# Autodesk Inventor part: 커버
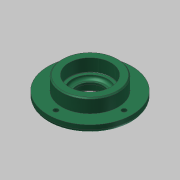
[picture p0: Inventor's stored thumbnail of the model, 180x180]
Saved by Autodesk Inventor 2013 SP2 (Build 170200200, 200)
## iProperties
Company: 한국ATC센터
Created: 2014-10
Part Number: 커버
Document SubType Name: Modeling
Designer: KYOUNG IL JANG
Density: 2.71 g/cm^3
Mass: 121.214 g
Surface Area: 161.165 cm^2
Volume: 44.7286 cm^3
Material: 알루미늄 6061
Author: KYOUNG IL JANG
Revision Number: 1
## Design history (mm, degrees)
sketch "스케치1"
  geometry: C1 r 41 at (0, 0); 1 further point
  constraints: 1 centre point, 1 coincident
  dimensions: "d0" = 82 diameter of C1
extrude "돌출1" new body sketch "스케치1" distance "d1" = 7; taper "d2" = 0 deg
sketch "스케치2"
  geometry: C1 r 27 at (0, 0); 1 further point
  constraints: 1 centre point, 1 coincident
  dimensions: "d3" = 54 diameter of C1
extrude "돌출2" join sketch "스케치2" distance "d4" = 13; taper "d5" = 0 deg
sketch "스케치3"
  geometry: C1 r 20 at (0, 0); 1 further point
  constraints: 1 centre point, 1 coincident
  dimensions: "d6" = 40 diameter of C1
extrude "돌출3" join sketch "스케치3" distance "d7" = 5; taper "d8" = 0 deg
hole "구멍1" diameter "d11" = 25; stored, may be unused: countersink angle "d15" = 90 deg, drill point angle "d17" = 118 deg; dims "d9" = 10, "d10" = 10, "d12" = 6, "d13" = 32, "d14" = 8.3, "d16" = 8
hole "구멍2" diameter "d20" = 34; stored, may be unused: countersink angle "d24" = 90 deg, drill point angle "d26" = 0 deg; dims "d18" = 10, "d19" = 10, "d21" = 6, "d22" = 40, "d23" = 12, "d25" = 3
fillet "모깎기2" dims "d34" = 3
fillet "모깎기1" dims "d27" = 0.3
chamfer "모따기1" distance "d28" = 1; stored, may be unused: second distance "d29" = 2, angle "d30" = 45 deg
chamfer "모따기2" distance "d31" = 1.2; stored, may be unused: second distance "d32" = 2, angle "d33" = 30 deg
sketch "스케치4" dims "d35" = 66
  geometry: 3 further points
  constraints: 2 horizontal alignment, 1 coincident, 2 other
hole "구멍3" sketch "스케치4" at (33, 0) diameter "d36" = 4.5; stored, may be unused: countersink angle "d40" = 90 deg, drill point angle "d42" = 118 deg; dims "d37" = 6, "d38" = 8, "d39" = 4.4, "d41" = 13
node "솔리드1"
pattern_circular "원형 패턴1" dims angle "d44" = 360 deg
